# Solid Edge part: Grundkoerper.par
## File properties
Author: helmut
Template: Normal.par
Last saved by: helmut
Revision: 11
Application: Solid Edge
Genauigkeit: 0,99
Teilflächenrmatvorlage: Model Default
Coef. of Thermal Exp: 0.0
Thermal Conductivity: 0.0
Specific Heat: 0.0
Modulus of Elasticity: 0.0
Poission's Ratio: 0.0
Yield Stress: 0.0
Ultimate Stress: 0.0
Elongation: 0.0
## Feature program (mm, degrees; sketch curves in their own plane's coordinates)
sketch for "unnamed Protrusion 1" plane through (0, 0, 0) normal (0, -1, 0) x-axis (1, 0, 0)
  line (-19.1928, 0) -> (80.8072, 0)
  line (80.8072, 0) -> (80.8072, 37.5)
  line (80.8072, 37.5) -> (40.8072, 37.5)
  line (40.8072, 37.5) -> (40.8072, 33)
  line (40.8072, 33) -> (50.8072, 33)
  line (50.8072, 33) -> (50.8072, 23)
  line (50.8072, 23) -> (10.8072, 23)
  line (10.8072, 23) -> (10.8072, 33)
  line (10.8072, 33) -> (20.8072, 33)
  line (20.8072, 33) -> (20.8072, 37.5)
  line (20.8072, 37.5) -> (-19.1928, 37.5)
  line (-19.1928, 37.5) -> (-19.1928, 0)
  dimension (linear) = 19.1928
  dimension (linear) = 80.8072
  dimension (linear) = 19.1928
  dimension (linear) = 80.8072
  dimension (linear) = 40.8072
  dimension (linear) = 10.8072
  dimension (linear) = 20.8072
  dimension (linear) = 10.8072
  dimension (linear) = 40.8072
  dimension (linear) = 20.8072
extrude "unnamed Protrusion 1" add finite 145 along -normal
sketch for "Ausprägung_2" plane through (30.8072, 0, 18.75) normal (0, -1, 0) x-axis (1, 0, 0)
  line (-20, -18.75) -> (-20, -8.75)
  line (-20, -8.75) -> (20, -8.75)
  line (20, -8.75) -> (20, -18.75)
  dimension (linear) = 20
  dimension (linear) = 20
extrude "Ausprägung_2" add finite 150 along +normal
sketch for "Bohrung_1" plane through (30.8072, -75, 10) normal (0, 0, 1) x-axis (0, 1, 0)
  hole centre (-35, 0) bore radius 5
hole "Bohrung_1" diameter 10 through
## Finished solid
Body 1: solid body, 19 faces, 50 edges, 32 vertices.
  Faces by surface: plane 18, cylinder 1
  Edges by curve: line 48, circle 2
Bounding box of the edges (mm): 100.000 x 295.000 x 37.500, from (-19.1928, -150, 0) to (80.8072, 145, 37.5).
Cylindrical faces by radius (mm): R5 x1
Planar faces by outward normal: +x 4, +y 1, +z 4, -x 4, -y 2, -z 3
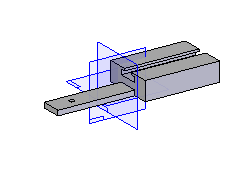
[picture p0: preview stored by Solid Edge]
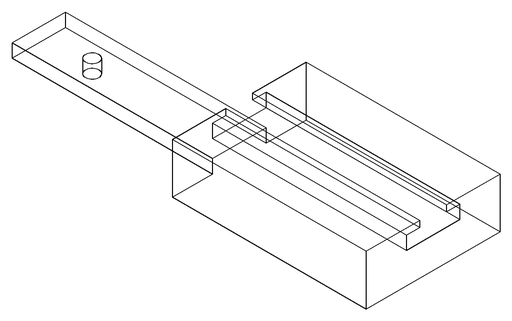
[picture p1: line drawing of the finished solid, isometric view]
